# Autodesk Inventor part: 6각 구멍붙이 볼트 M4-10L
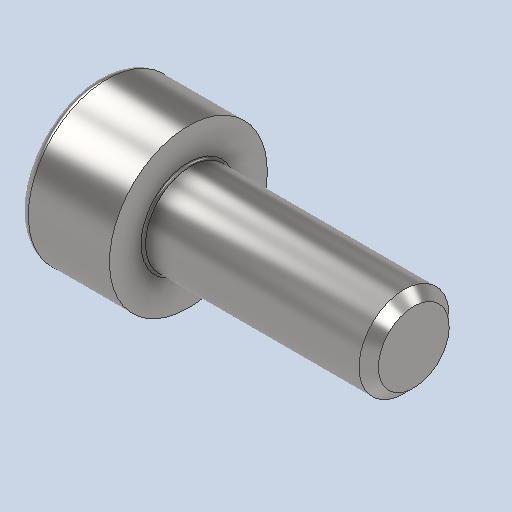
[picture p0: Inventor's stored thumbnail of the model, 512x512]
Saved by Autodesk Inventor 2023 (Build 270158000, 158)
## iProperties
Created: 2025-04
Part Number: 6각 구멍붙이 볼트 M4-10L
Material: 강철, 연강
Description: 6각머리 태핑 나사
Document SubType Name: Modeling
Designer: User
Density: 7.86 g/cm^3
Appearance: 기본값
Author: jhkim
Revision Number: 1
Sending System: Autodesk Inventor 2026
Preprocessor: ST-DEVELOPER v20.1
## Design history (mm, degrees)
feature "Solid1"
node "솔리드1"
